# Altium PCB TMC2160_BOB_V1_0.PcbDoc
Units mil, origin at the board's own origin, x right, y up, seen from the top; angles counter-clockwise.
Board outline 1500 x 1100 mil, 4 copper layers (Top, GND, VM, Bottom), stack 63.504 mil thick; 46 components, 52 nets, 171 pads, 147 vias.
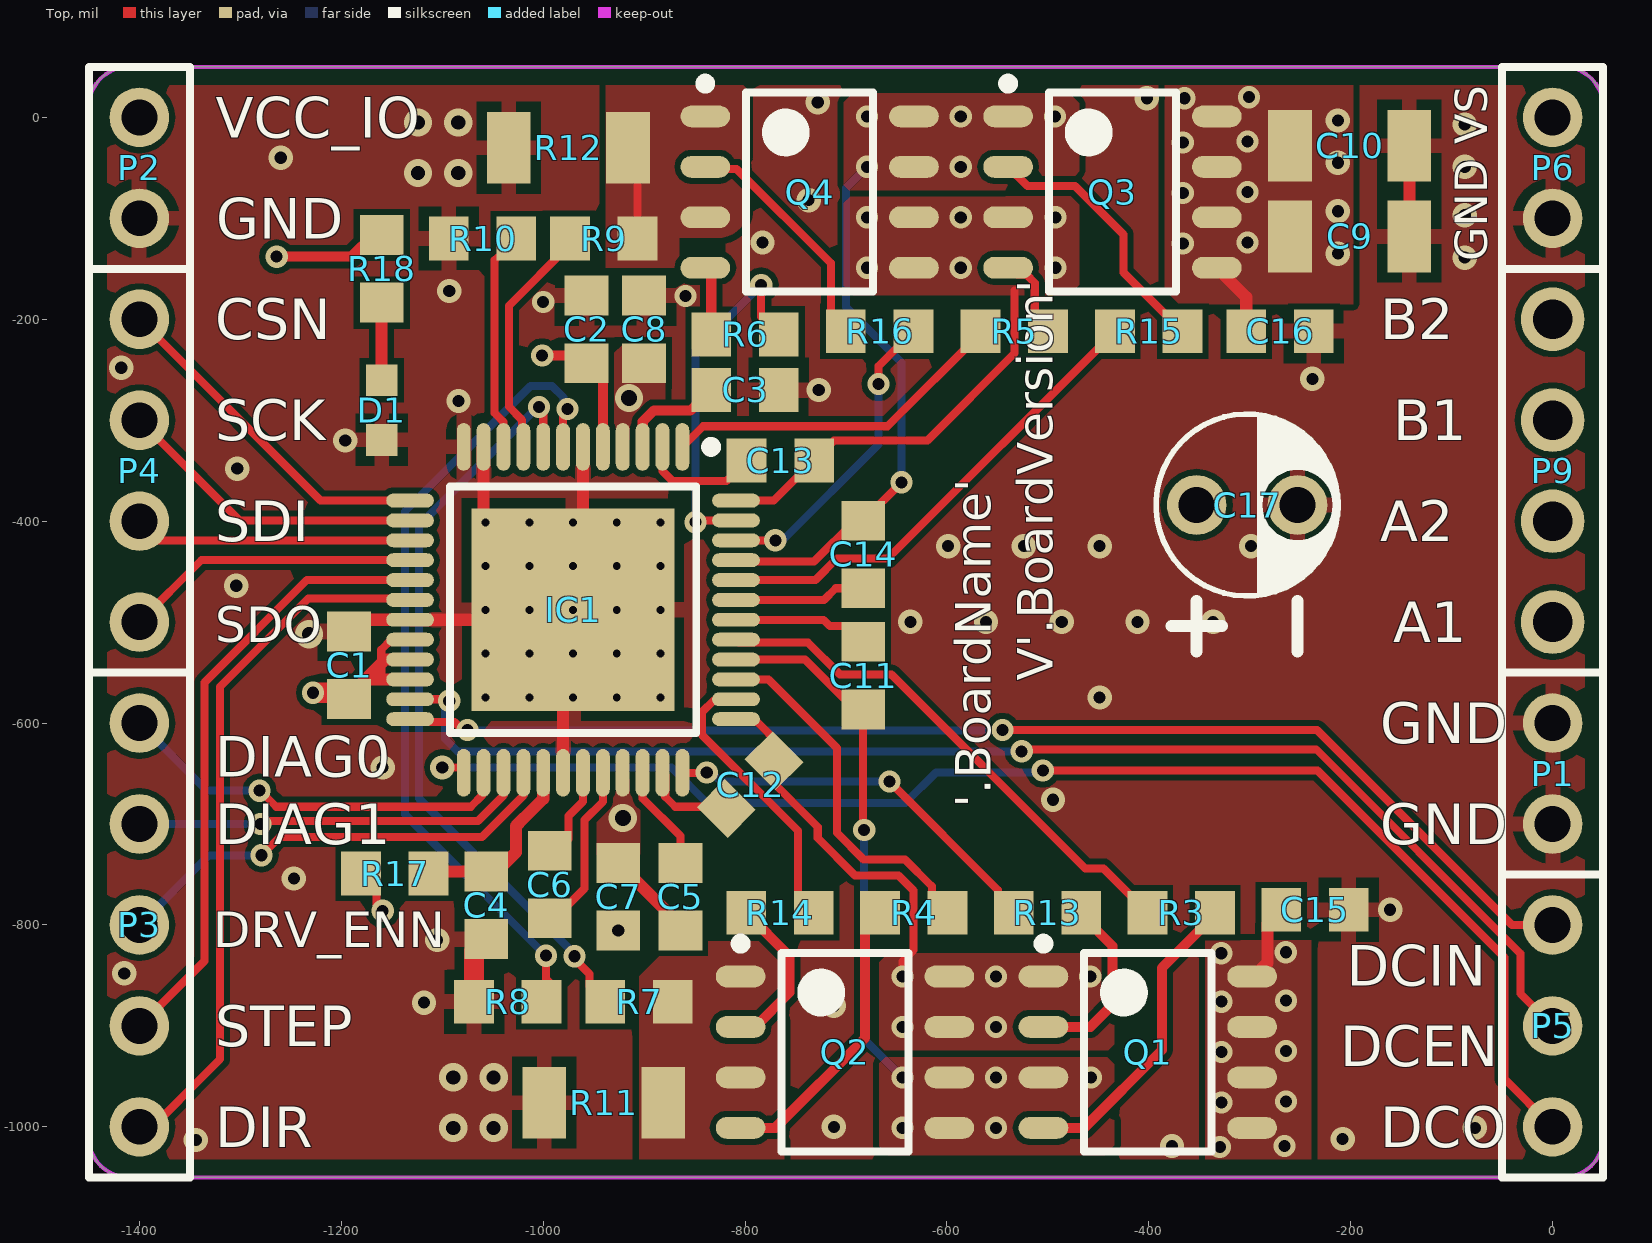
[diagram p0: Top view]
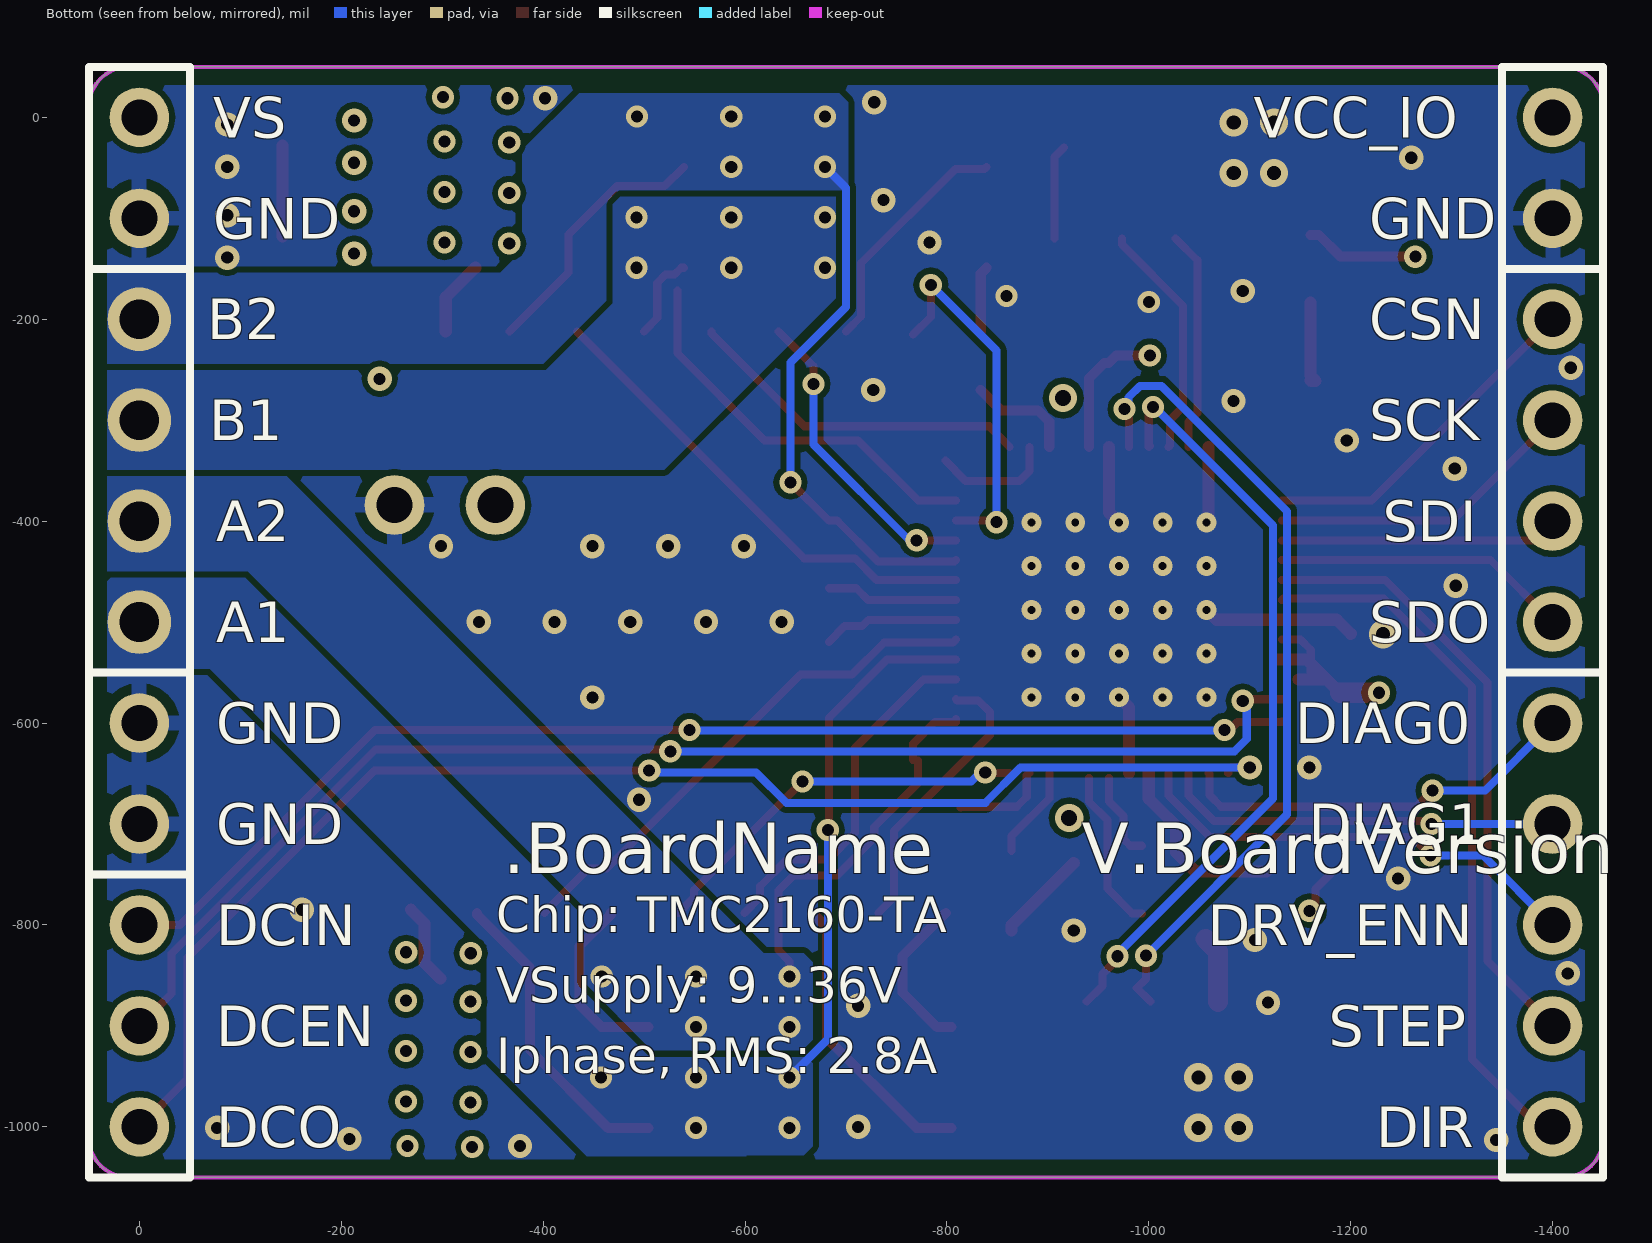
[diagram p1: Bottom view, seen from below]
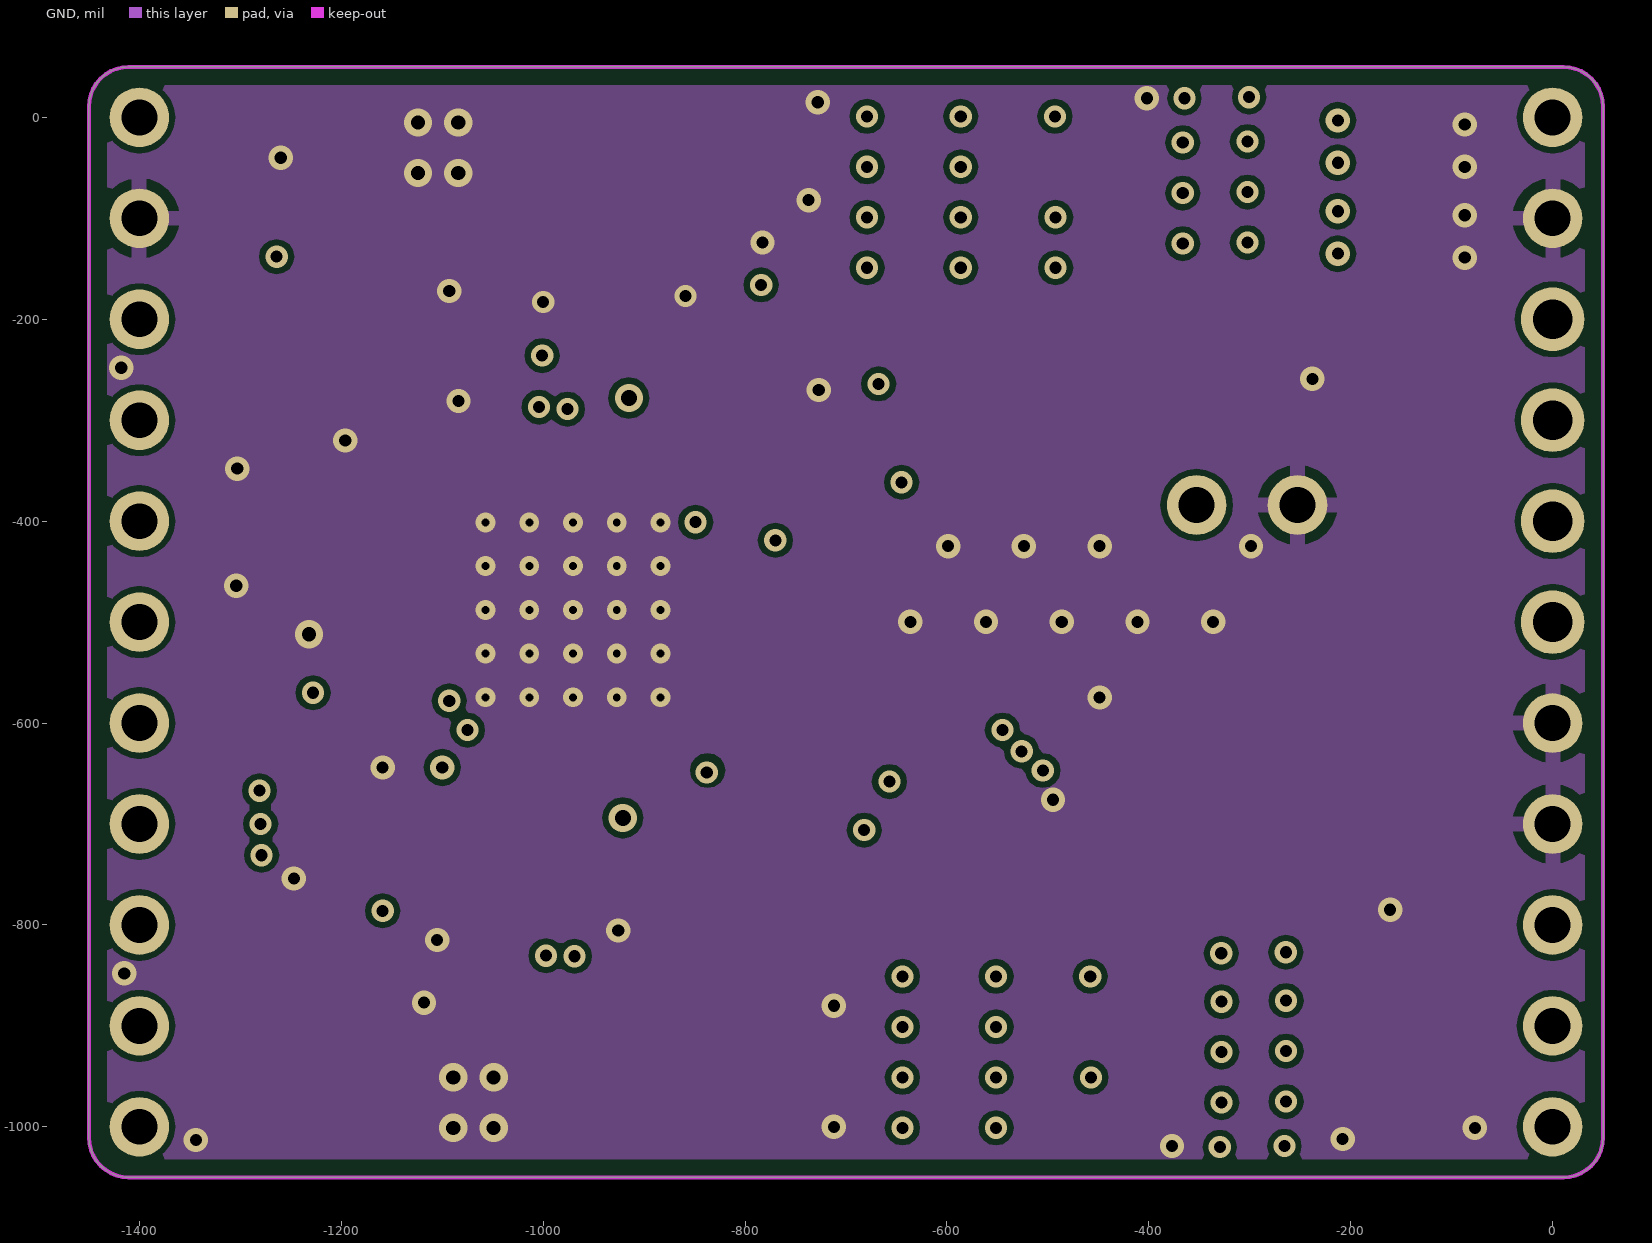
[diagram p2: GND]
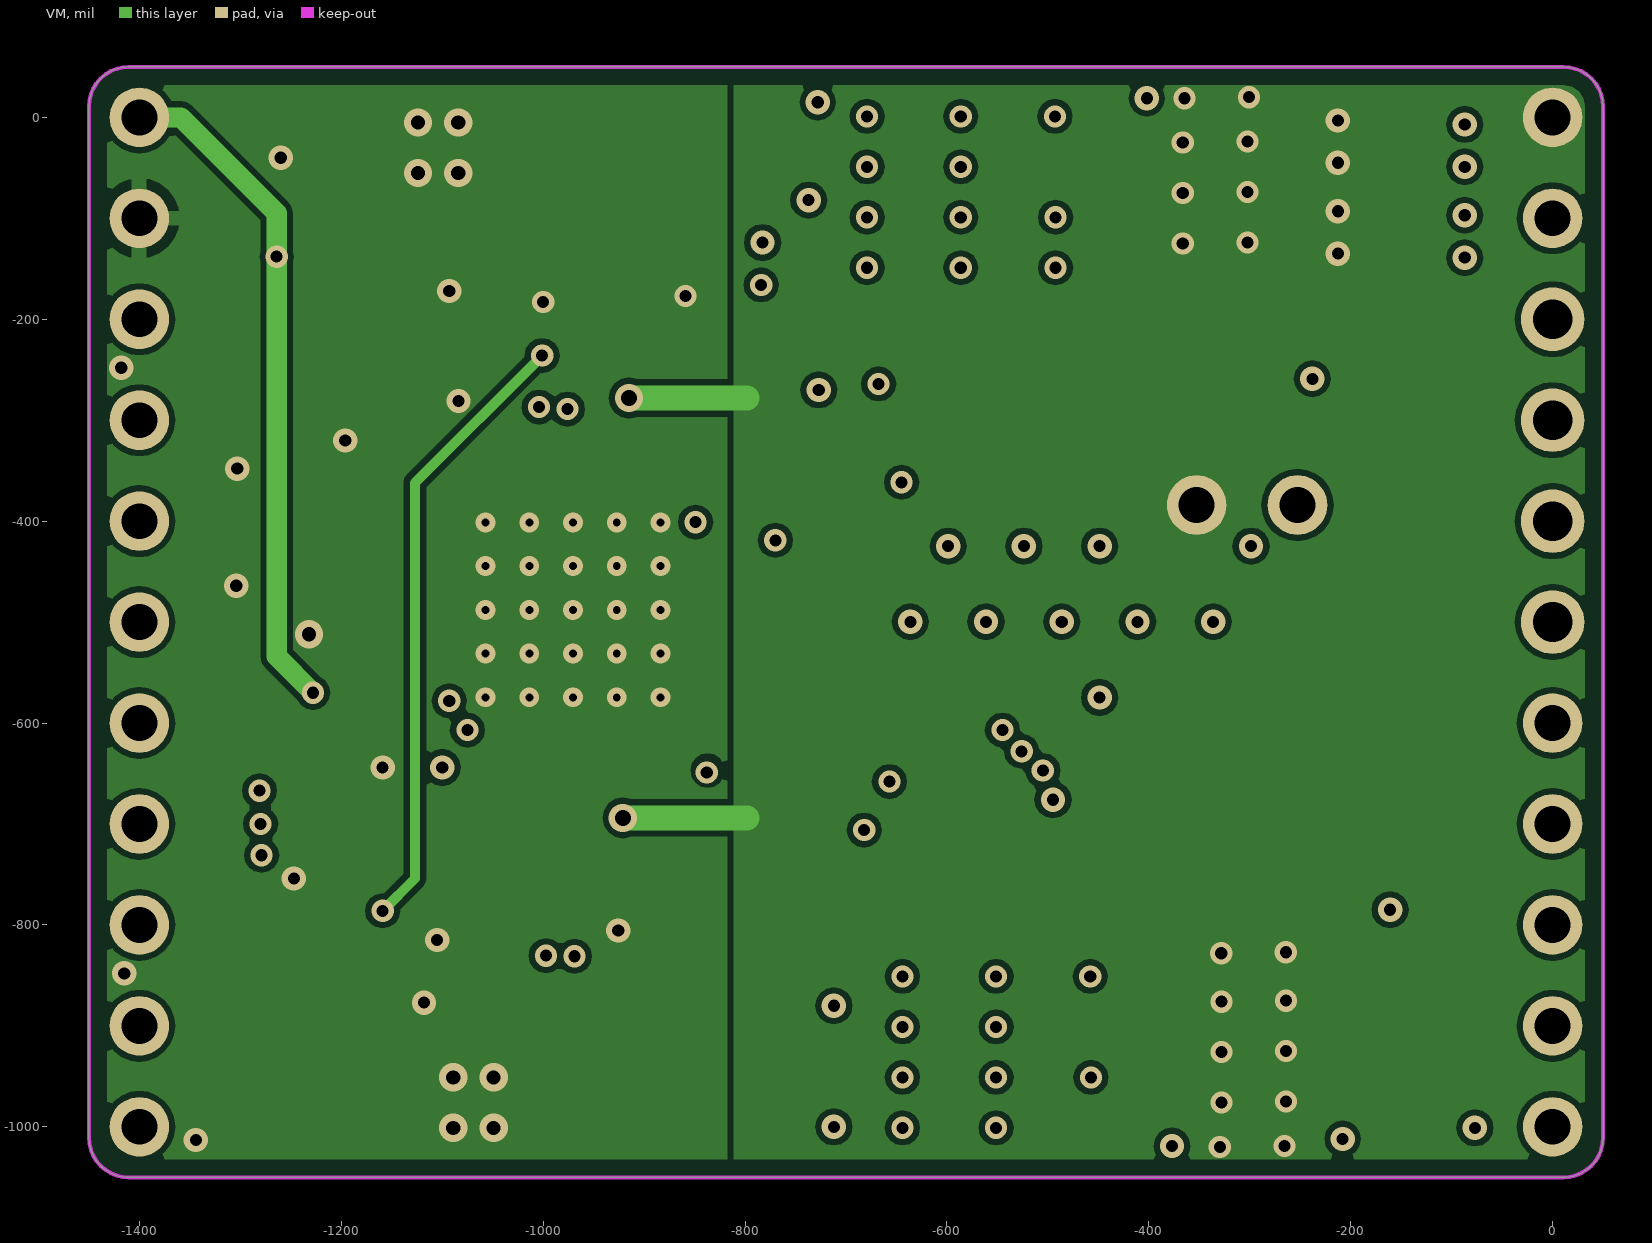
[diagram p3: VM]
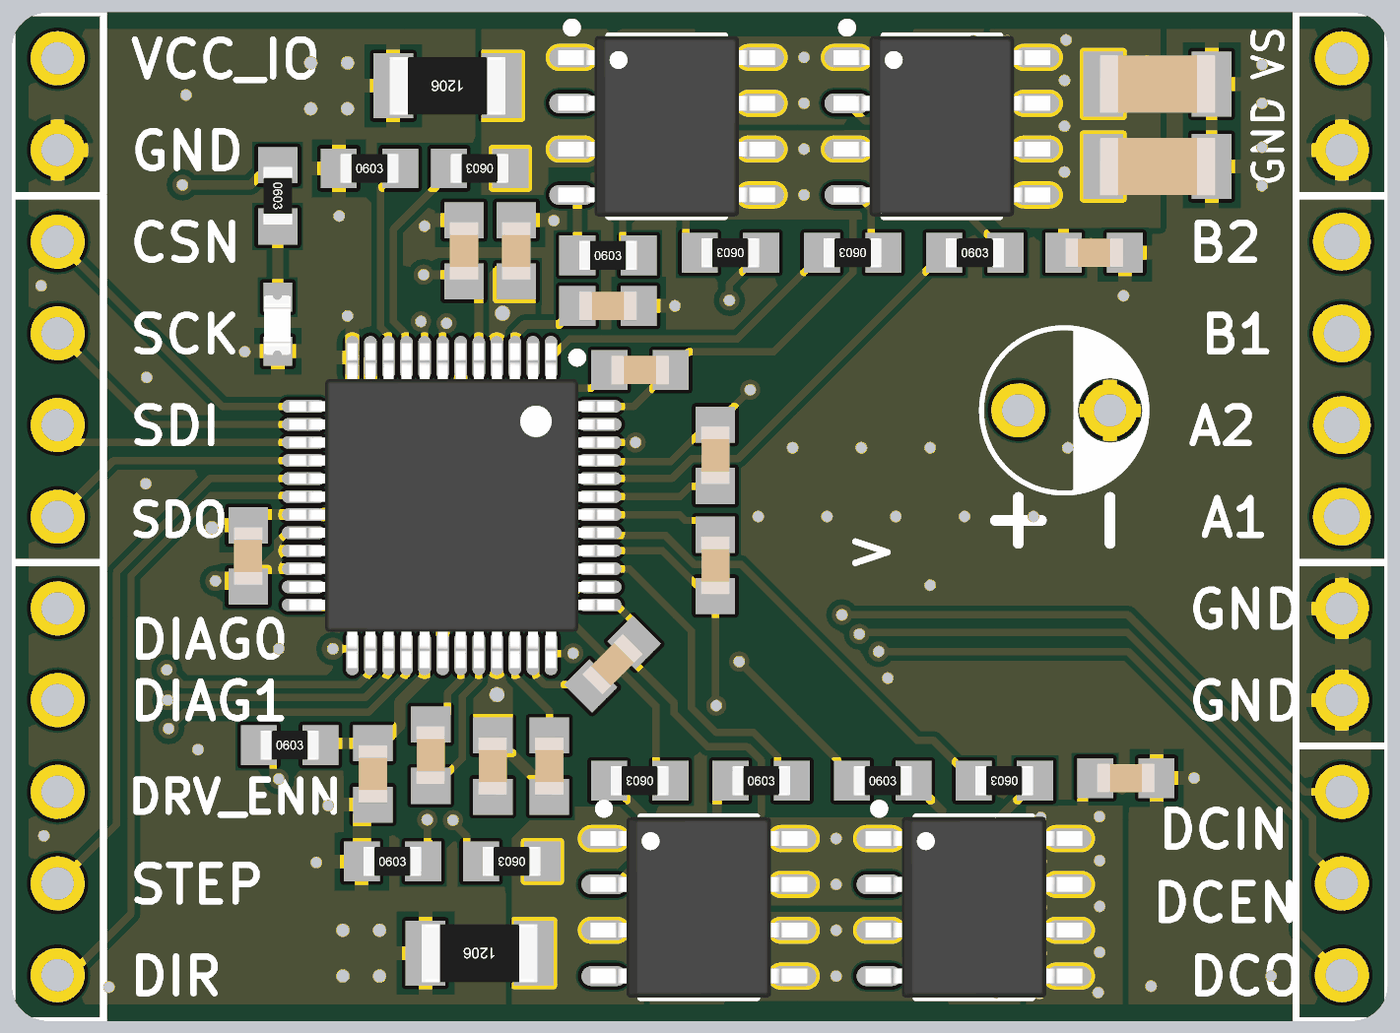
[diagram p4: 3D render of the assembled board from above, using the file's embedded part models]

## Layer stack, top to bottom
Top Solder: solder mask 0.4, Solder Resist, Dk 3.5
Top: signal copper 0.689
Dielectric 1: core 10, FR-4, Dk 4.8
GND: signal copper 1.378
Dielectric 2: prepreg 39.3701, FR-4, Dk 4.2
VM: signal copper 1.378
Dielectric4: core 10, FR-4, Dk 4.2
Bottom: signal copper 0.689
Bottom Solder: solder mask 0.4, Solder Resist, Dk 3.5

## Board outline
-1450,-1010.63 ccw(c-1410.63,-1010.63) -1410.63,-1050 10.63,-1050 ccw(c10.63,-1010.63) 50,-1010.63 50,10.63 ccw(c10.63,10.63) 10.63,50 -1410.63,50 ccw(c-1410.63,10.63) -1450,10.63

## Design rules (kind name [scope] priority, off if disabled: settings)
Clearance BoardOutlineClearance [OnLayer('Keep-Out Layer')] p1: gap=15.75 ignorepadtopadclearanceinfootprint=FALSE except(0: Arc-Hole Track-Hole SMDPad-Hole THPad-Hole Via-Hole Fill-Hole Poly-Hole Region-Hole Text-Hole)
Clearance "Fiducial Clearance" [HasFootprint('FIDUCIAL_40MIL')] p2: gap=26 ignorepadtopadclearanceinfootprint=FALSE except(0: Arc-Hole Track-Hole SMDPad-Hole THPad-Hole Via-Hole Fill-Hole Poly-Hole Region-Hole Text-Hole)
Clearance "Mounting Hole Clearance" [(HoleDiameter >= 110) And  IsPad  And ((PadYSize_AllLayers - HoleDiameter)  <=  1)] p3: gap=30 ignorepadtopadclearanceinfootprint=FALSE except(0: Arc-Hole Track-Hole SMDPad-Hole THPad-Hole Via-Hole Fill-Hole Poly-Hole Region-Hole Text-Hole)
Clearance [All] p4: gap=6 ignorepadtopadclearanceinfootprint=TRUE except(0: Arc-Hole Track-Hole SMDPad-Hole THPad-Hole Via-Hole Fill-Hole Poly-Hole Region-Hole Text-Hole)
ComponentClearance Pinheader2PinheaderClearance [InComponentClass('Pinheader') vs InComponentClass('Pinheader')] p1: gap=0 collisioncheckmode=3 verticalgap=0 showdistances=FALSE
ComponentClearance [All] p2: gap=0 collisioncheckmode=3 verticalgap=100000 showdistances=FALSE
DiffPairsRouting [All] p1 off: maxlimit=10 minlimit=7.5 mostfreqgap=10 toplayer_prefgap=7.5 toplayer_minwidth=7.5 toplayer_maxwidth=7.5 toplayer_prefwidth=7.5 midlayer1_prefgap=7.5 midlayer1_minwidth=7.5 midlayer1_maxwidth=7.5 midlayer1_prefwidth=7.5 midlayer2_mingap=10 midlayer2_minwidth=15 midlayer2_maxwidth=15 midlayer2_prefwidth=15 bottomlayer_prefgap=7.5 bottomlayer_minwidth=7.5 bottomlayer_maxwidth=7.5 bottomlayer_prefwidth=7.5 maxuncoupledlength=500
HoleSize [All] p1: absolutevalues=TRUE maxlimit=100000 minlimit=7.87 maxpercent=80.000 minpercent=20.000
HoleToHoleClearance [All] p1: gap=8 allowstackedmicrovias=TRUE
MatchedLengths "SD_CARD MatchedLengths" [InNetClass('SD_CARD')] p1: tolerance=10 checknetsindiffpair=FALSE checkdiffpairvsdiffpair=TRUE checkxsignals=TRUE checkothers=TRUE
MinimumAnnularRing MinimumViaAnnualRing [All] p1: minimumring=4.92
MinimumSolderMaskSliver STM32_MinimumSolderMaskSliver [(InComponent('STM1') AND InComponent('STM2')) vs (InComponent('STM1') AND InComponent('STM2'))] p1: minsoldermaskwidth=1
MinimumSolderMaskSliver USB_HUB_MinimumSolderMaskSliver [InComponent('USB_HUB')] p2: minsoldermaskwidth=1
MinimumSolderMaskSliver [All] p3 off: minsoldermaskwidth=1.5
PasteMaskExpansion TestPadPasteMaskExpansion [HasFootprint('SMD_TP_2X2_ROUND')] p1: expansion=-78.74
PasteMaskExpansion [All] p2: expansion=0
PolygonConnect SA_SB_PolygonConnect [InNet('SA') OR InNet('SB')] p1: connectstyle=Direct reliefconductorwidth=70 reliefentries=4 polygonreliefangle="90 Angle" airgapwidth=10
PolygonConnect VM_PolygonConnect [InNet('+VM')] p2: connectstyle=Direct reliefconductorwidth=70 reliefentries=4 polygonreliefangle="90 Angle" airgapwidth=10
PolygonConnect ThermalVias [IsVia] p3: connectstyle=Direct reliefconductorwidth=10 reliefentries=4 polygonreliefangle="90 Angle" airgapwidth=10
PolygonConnect MotorOutputConStyle [InNetClass('MotorPowerOut')] p4: connectstyle=Direct reliefconductorwidth=10 reliefentries=4 polygonreliefangle="90 Angle" airgapwidth=10
PolygonConnect [All] p5: connectstyle=Relief reliefconductorwidth=15 reliefentries=4 polygonreliefangle="90 Angle" airgapwidth=10
RoutingVias [All] p1: holewidth=12 width=22 viastyle="Through Hole" minholewidth=12 minwidth=22 maxholewidth=12 maxwidth=50
ShortCircuit [All] p1 off: allowed=FALSE
SilkToBoardRegionClearance [All] p1 off:
SilkToSilkClearance [All] p1 off: silktosilkclearance=10
SilkToSolderMaskClearance [IsPad] p1 off: minsilkscreentomaskgap=10 clearancetoexposedcopper=TRUE
SolderMaskExpansion FiducialSolderMaskExpansion [HasFootprint('FIDUCIAL_40MIL')] p1: expansion=26
SolderMaskExpansion [All] p2: expansion=4
UnRoutedNet [All] p1 off:
Width VIN_Width [InNetClass('PWR_VIN')] p1: maxlimit=300 minlimit=200 preferedwidth=210
Width Other_Width [All] p2: maxlimit=100000 minlimit=8 preferedwidth=11.81 minimp=50.000000 maximp=50.000000 favimp=50.000000
19 further rules are at their usual default settings.

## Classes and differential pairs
net class MotorPowerOut: BMA1 BMA2 BMB1 BMB2

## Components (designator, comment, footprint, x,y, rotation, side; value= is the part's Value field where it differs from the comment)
C1 "100nF" C0603 -1192.26,-542.78 r90 top
C2 "2u2" C0603 -957,-210 r90 top
C3 "2u2" C0603 -800,-270 r180 top
C4 "470nF" C0603 -1056.33,-780.54 r270 top
C5 "100nF" C0603 -864,-772 r90 top
C6 "22nF" C0603 -993.33,-760 r270 top
C7 "100nF" C0603 -925.67,-772 r270 top
C8 "100nF" C0603 -900,-210 r90 top
C9 "10uF/50V/10%" C1206 -201,-118 r180 top
C10 "10uF/50V/10%" C1206 -201,-28 r180 top
C11 "220nF" C0603 -683,-553 r270 top
C12 "220nF" C0603 -795.06,-661 r45 top
C13 "220nF" C0603 -765,-340 r0 top
C14 "220nF" C0603 -683,-433 r90 top
C15 "470nF/50V" C0603 -235.46,-785 r0 top
C16 "470nF/50V" C0603 -270,-212 r0 top
C17 "Cap Pol1" EXT_POL_CAP -352.68,-384 r270 top value="ELKO 100uF/low-ESR"
D1 "LED, Blue, SMD, 20mA, 2.8V, 465 nm" LED_0603 -1160,-290 r270 top
IC1 "TMC2160-TA" TMC5160_TSQFP50P900X900X120_HS-49L -970.42,-487.87 r270 top
P1 "GND" 2_PIN_THT 0,-700 r0 top
P2 "VCC_IO" 2_PIN_THT -1400,-100 r0 top
P3 "MISC" 5_PIN_THT -1400,-1000 r0 top
P4 "SPI" 4_PIN_THT -1400,-200 r180 top
P5 "DCSTEP" 3_PIN_THT 0,-1000 r0 top
P6 "VM" 2_PIN_THT 0,-100 r0 top
P9 "MAB" 4_PIN_THT_1mm_hole 0,-200 r180 top
Q1 "AO4882" SOP127P600X170-8L -401.03,-926 r0 top
Q2 "AO4882" SOP127P600X170-8L -701.03,-926 r0 top
Q3 "AO4882" SOP127P600X170-8L -436.03,-74 r0 top
Q4 "AO4882" SOP127P600X170-8L -736.03,-74 r0 top
R3 "22R / 100mW / 1%" R0603 -367.97,-788 r180 top
R4 "22R / 100mW / 1%" R0603 -632.96,-788 r0 top
R5 "22R / 100mW / 1%" R0603 -533.33,-212 r180 top
R6 "22R / 100mW / 1%" R0603 -800,-215 r0 top
R7 "47R /  / 1%" R0603 -905,-876 r180 top
R8 "47R /  / 1%" R0603 -1035,-876 r0 top
R9 "47R /  / 1%" R0603 -940,-120 r180 top
R10 "47R /  / 1%" R0603 -1060,-120 r0 top
R11 "75mR" R1206 -940,-976 r180 top
R12 "75mR" R1206 -975,-30 r180 top
R13 "22R / 100mW / 1%" R0603 -500.47,-788 r0 top
R14 "22R / 100mW / 1%" R0603 -765.46,-788 r180 top
R15 "22R / 100mW / 1%" R0603 -400,-212 r0 top
R16 "22R / 100mW / 1%" R0603 -666.67,-212 r180 top
R17 "2R2/1%/" R0603 -1147,-749.04 r0 top
R18 "1k" R0603 -1160,-150 r270 top

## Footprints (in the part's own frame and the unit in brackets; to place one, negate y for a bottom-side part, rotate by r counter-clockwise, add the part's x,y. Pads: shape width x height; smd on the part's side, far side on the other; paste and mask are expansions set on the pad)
2_PIN_THT [mm]
  round 1.5 hole 0.9: 1(0,0) 2(0,2.54)
  silkscreen extent -1.27,-1.27 1.27,3.81
3_PIN_THT [mm]
  round 1.5 hole 0.9: 1(0,0) 2(0,2.54) 3(0,5.08)
  silkscreen extent -1.27,-1.27 1.27,6.35
4_PIN_THT [mm]
  round 1.5 hole 0.9: 1(0,0) 2(0,2.54) 3(0,5.08) 4(0,7.62)
  silkscreen extent -1.27,-1.27 1.27,8.89
4_PIN_THT_1mm_hole [mm]
  round 1.6 hole 1: 1(0,0) 2(0,2.54) 3(0,5.08) 4(0,7.62)
  silkscreen extent -1.27,-1.27 1.27,8.89
5_PIN_THT [mm]
  round 1.5 hole 0.9: 1(0,0) 2(0,2.54) 3(0,5.08) 4(0,7.62) 5(0,10.16)
  silkscreen extent -1.27,-1.27 1.27,11.43
C0603 [mm] "0603 ceramic capacitor"
  rect 1x1.1 smd: 1(-0.85,0) 2(0.85,0)
  body extent -0.8,-0.4 0.8,0.4, height 0.8
C1206 [mm] "1206 ceramic capacitor"
  rect 1.1x1.8 smd: 1(-1.5,0) 2(1.5,0)
  body extent -1.6,-0.8 1.6,0.8, height 0.76
EXT_POL_CAP [mm]
  round 1.5 hole 0.9: 1(0,0) 2(0,2.54)
  silkscreen extent -2.29,-1.02 3.68,3.56
LED_0603 [mm]
  rect 0.8x0.8 smd: 1(-0.75,0) 2(0.75,0)
  body extent -0.8,-0.38 0.85,0.35, height 0.68
R0603 [mm] "0603 resistor"
  rect 1x1.1 smd: 1(-0.85,0) 2(0.85,0)
  body extent -0.8,-0.4 0.8,0.4, height 0.45
R1206 [mm] "1206 resistor"
  rect 1.1x1.8 smd: 1(-1.5,0) 2(1.5,0)
  body extent -1.6,-0.8 1.6,0.8, height 0.6
SOP127P600X170-8L [mm] "SOP, 8-Leads, Body 4,90x3,90mm, Pitch 1,27mm, IPC High Density"
  oval 1.25x0.55 smd: 1(-2.625,1.905) 2(-2.625,0.635) 3(-2.625,-0.635) 4(-2.625,-1.905) 5(2.625,-1.905) 6(2.625,-0.635) 7(2.625,0.635) 8(2.625,1.905)
  silkscreen extent -2.75,-2.5 1.6,2.85, body extent -3,-2.5 3,2.5, height 1.7
TMC5160_TSQFP50P900X900X120_HS-49L [mm] "TSQFP, 48-Leads, Body 7,00x7,00mm, Pitch 0,50mm, Thermal Pad 5,10x5,10mm, IPC High Density"
  oval 1.2x0.35 smd mask+0.102: 1(-4.1,2.75) 2(-4.1,2.25) 3(-4.1,1.75) 4(-4.1,1.25) 5(-4.1,0.75) 6(-4.1,0.25) 7(-4.1,-0.25) 8(-4.1,-0.75) 9(-4.1,-1.25) 10(-4.1,-1.75) 11(-4.1,-2.25) 12(-4.1,-2.75) 25(4.1,-2.75) 26(4.1,-2.25) 27(4.1,-1.75) 28(4.1,-1.25) 29(4.1,-0.75) 30(4.1,-0.25) 31(4.1,0.25) 32(4.1,0.75) 33(4.1,1.25) 34(4.1,1.75) 35(4.1,2.25) 36(4.1,2.75)
  oval 0.35x1.2 smd mask+0.102: 13(-2.75,-4.1) 14(-2.25,-4.1) 15(-1.75,-4.1) 16(-1.25,-4.1) 17(-0.75,-4.1) 18(-0.25,-4.1) 19(0.25,-4.1) 20(0.75,-4.1) 21(1.25,-4.1) 22(1.75,-4.1) 23(2.25,-4.1) 24(2.75,-4.1) 37(2.75,4.1) 38(2.25,4.1) 39(1.75,4.1) 40(1.25,4.1) 41(0.75,4.1) 42(0.25,4.1) 43(-0.25,4.1) 44(-0.75,4.1) 45(-1.25,4.1) 46(-1.75,4.1) 47(-2.25,4.1) 48(-2.75,4.1)
  rect 5.1x5.1 smd: 49(0,0)
  silkscreen extent -4.22,-3.1 3.1,3.6, body extent -4.5,-4.5 4.5,4.5, height 1.2

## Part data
C1 C7 C8: library part Capacitor, "Ceramic capacitor", Manufacturer=Multicomp, MPN=MC0603F104M500CT, Voltage rating=50V
C2 C3: library part "2.2 µF, 25 V, ± 10%, X5R, GRM Series", "SMD Multilayer Ceramic Capacitor, 0603 [1608 Metric], 2.2 µF, 25 V, ± 10%, X5R, GRM Series", MPN=GRM188R61E225KA12D, Voltage rating=50V
C4: library part Capacitor, "Ceramic capacitor", MPN=MC0603X474K160CT, Voltage rating=16V
C5: library part Capacitor, "Ceramic capacitor", MPN=MC0603F104M500CT, Voltage rating=50V
C6: library part Capacitor, "Ceramic capacitor", MPN=MC0603B223K500CT, Voltage rating=50V
C9 C10: library part "10 µF, 50 V, ± 20%, X5R, GRM Series", "SMD Multilayer Ceramic Capacitor, 1206 [3216 Metric], 10 µF, 50 V, ± 20%, X5R, GRM Series", Capacitance=10uF, MPN=GRM31CR61H106MA12L, VoltageRating=50V
C11 C12 C13 C14: library part "0.22 µF, 50 V, ± 10%, X7R", "SMD Multilayer Ceramic Capacitor, 0603 [1608 Metric], 0.22 µF, 50 V, ± 10%, X7R, GCM Series", MPN=GCM188R71H224KA64D, Voltage rating=50V
C15 C16: library part "0.47 µF, 50 V, ± 10%, X7R, C Series", "SMD Multilayer Ceramic Capacitor, 0603 [1608 Metric], 0.47 µF, 50 V, ± 10%, X7R, C Series", Capacitance=470nF, MPN=C1608X7R1H474K080AC, VoltageRating=50V
C17: "Polarized Capacitor (Radial)"
D1: Colour=Blue, Current rating=20mA, MPN=LTST-C191TBKT-5A
IC1: Manufacturer=TRINAMIC
P1 P2 P6: library part "Header 2", "Header, 2-Pin"
P3: library part "Header 5", "Header, 5-Pin"
P4: library part "Header 4", "Header, 4-Pin"
P5: library part "Header 3", "Header, 3-Pin"
P9: library part "Wire-To-Board Connector, 2.5 mm, 4 Contacts, Header, EH Series, Through Hole, 1 Rows", "Wire-To-Board Connector, 2.5 mm, 4 Contacts, Header, EH Series, Through Hole, 1 Rows", MPN=B4B-EH-A
Q1 Q2 Q3 Q4: library part "AO4882 MOSFET 2N-CH 40V 8A 8SOIC", "Mosfet Array 2 N-Channel (Dual) 40V 8A 2W Surface Mount 8-SOIC"
R3 R4 R5 R6 R13 R14 R15 R16: library part "22 ohm, 50 V, 0603 [1608 Metric], 100 mW, ± 1%, MCWR Series", "SMD Chip Resistor, Thick Film, 22 ohm, 50 V, 0603 [1608 Metric], 100 mW, ± 1%, MCWR Series", MPN=MCWR06X22R0FTLV, PowerRating=100mW, Resistance=22R, Temp coefficient=*ppm
R7 R8 R9 R10: library part "47 ohm, 75 V, 0603 [1608 Metric], 100 mW, ± 1%, MCSR 06 Series", "SMD Chip Resistor, Ceramic, 47 ohm, 75 V, 0603 [1608 Metric], 100 mW, ± 1%, MCSR 06 Series", MPN=MCSR06X47R0FTL, Resistance=47R, Temp coefficient=*ppm
R11 R12: library part "R_SENS, 0.075 ohm, 1206, 1W, ± 1%, ERJ Series", "SMD Chip Resistor, Thick Film, Current Sense Resistors - SMD 1W 0.075ohm 1%", MPN=ERJ-8BWFR075V, PowerRating=1W, Temp coefficient=*ppm, VoltageRating=50V
R17: library part Resistor, "Resistor", MPN=MC0063W060312R2, Power rating=*mW, Resistance=2R2, Temp coefficient=*ppm, Voltage rating=*V
R18: library part "1 kohm, 50 V, 0603 [1608 Metric], 63 mW, ± 1%, MC Series", "1 kohm, 50 V, 0603 [1608 Metric], 63 mW, ± 1%, MC Series", MPN=MC0063W060311K, PowerRating=63mW, Temp coefficient=*ppm, VoltageRating=50V

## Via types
v1: diameter 22, hole 12, Top to Bottom, tented both sides, 65 vias
v2: diameter 24.1, hole 12, Top to Bottom, tented both sides, 29 vias
v3: diameter 19.68, hole 7.87, Top to Bottom, tented bottom, 25 vias
v4: diameter 24, hole 12, Top to Bottom, tented both sides, 17 vias
v5: diameter 28, hole 14, Top to Bottom, tented both sides, 9 vias
v6: diameter 28, hole 16, Top to Bottom, tented both sides, 2 vias

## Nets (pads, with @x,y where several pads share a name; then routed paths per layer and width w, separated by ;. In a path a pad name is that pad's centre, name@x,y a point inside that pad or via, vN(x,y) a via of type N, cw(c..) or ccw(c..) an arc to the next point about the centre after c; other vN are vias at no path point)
5V_OUT: C2.1 IC1.5 R17.1 | length 798.9
  Top w8: R17.1 -1165,-764.5 -1165,-780 v1(-1159,-786)
  Top w10: v1(-1001,-236) -967.46,-236 -960,-243.46 -955.57,-243.46 -940.89,-258.15 IC1.5
  VM w10: v1(-1159,-786) -1127,-754 -1127,-362 v1(-1001,-236)
12VOUT: C3.2 IC1.3 | length 106.3
  Top w10: IC1.3 -901.32,-326.45 -901.32,-301.32 -890.23,-290.23 -854.08,-290.23 -853.88,-290.42 C3.2
+VM: C5.1 C7.1 C8.1 C9.2 C10.2 C15.1 C16.1 C17.1 IC1.4 IC1.33 P6.2 Q1.5 Q1.6 Q1.7 Q1.8 Q3.5 Q3.6 Q3.7 Q3.8 | length 487.7
  Top w12: C7.1 -864,-800.2 C5.1 ; Q3.5 -303.46,-178.22 C16.1 ; Q1.8@-298,-853 -282.61,-837.61 -282.61,-798.69 C15.1
  VM w25: v6(-921.06,-694) -798,-694 ; v6(-915.06,-278) -798,-278
  other v1: -329.68,-1020 -265.68,-1019 -328,-976 -264,-975 -328,-926 -264,-925 -328,-876 -264,-875 -328.32,-828 -264.32,-827 -366.37,-125 -302.37,-124 -366.37,-75 -302.37,-74 -366.37,-25 -302.37,-24 -364.68,19 -300.68,20
  other v4: -212.79,-135 -212.79,-93 -212.79,-45 -212.79,-3
BMA1: C11.2 IC1.40 P9.4 Q1.3 Q2.5 Q2.6 | length 522.8
  Top w8: IC1.40 -740.74,-537.08 -683,-594.81 -683,-705 v1(-682,-706)
  Bottom w8: v1(-682,-706) -682,-911.69 -682.68,-912.37 v1(-644.06,-951)
  other v1: -644.06,-1001 -551.31,-1001 -551.31,-951 -457.44,-951
BMA2: C12.2 IC1.37 P9.3 Q1.1 Q2.7 Q2.8 | length 371
  Top w8: IC1.37 -809,-599.02 -787.98,-599.02 -766.34,-620.66 C12.2@-766.34,-636.34 ; C12.2 -771.39,-659.61 -728,-703 -728,-714 -691,-751 -647.95,-751 -633,-765.95 -633,-825 -644.06,-836.06 v1(-644.06,-851)
  other v1: -644.06,-901 -551.31,-901 -551.31,-851 -458.01,-851
BMB1: C13.2 IC1.48 P9.2 Q3.3 Q4.5 Q4.6 | length 398.7
  Top w8: IC1.48 -771.6,-379.6 -712,-320 -619.32,-320 -533,-233.68 -533,-171.38
  other v1: -679.06,-149 -586.31,-149 -492.44,-149 -679.06,-99 -586.31,-99 -492.44,-99
BMB2: C14.2 IC1.45 P9.1 Q3.1 Q4.7 Q4.8 | length 541.1
  Top w8: IC1.45 -807.68,-439.97 -731.78,-439.97 -691.35,-399.54 C14.2 v1(-645,-361.54)
  Bottom w8: v1(-679.06,-49) -700.06,-70 -700.06,-187.74 -645,-242.8 v1(-645,-361.54)
  other v1: -586.31,-49 -679.06,1 -586.31,1 -493.01,1
CA1: C11.1 IC1.42 | length 135
  Top w8: IC1.42 -722.35,-497.71 -716.06,-504 -698.54,-504 C11.1
CA2: C12.1 IC1.35 | length 94.7
  Top w8: IC1.35 -879.04,-652.08 -879.04,-673.01 -869.14,-682.9 -814.42,-682.9 C12.1@-813.66,-683.66
CB1: C13.1 IC1.2 | length 119.5
  Top w8: IC1.2 -881.83,-350.21 -871.97,-360.07 -818.53,-360.07 C13.1
CB2: C14.1 IC1.43 | length 130.8
  Top w8: IC1.43 -721.71,-478.02 -710.15,-466.46 C14.1
CSN: IC1.13 P4.1 | length 342.6
  Top w8: P4.1 -1220.4,-379.6 IC1.13
DCEN: IC1.23 P5.2 | length 1326.6
  Top w8: IC1.23 -1094.55,-576.45 v1(-1093,-578) ; v1(-526,-628) -528,-628 -530,-626 -234.2,-626 -32,-828.2 -32,-868 P5.2
  Bottom w8: v1(-1093,-578) -1093,-581.79 -1097,-585.79 -1097,-615.82 -1084.82,-628 v1(-526,-628)
DCIN: IC1.24 P5.3 | length 1221.4
  Top w8: IC1.24@-1131.83,-598.26 -1131.09,-599 -1087.66,-599 -1076,-610.66 -1075,-609.66 v1(-1075,-607) ; v1(-545,-607) -233.4,-607 -40.4,-800 P5.3
  Bottom w8: v1(-1075,-607) -1075.5,-607.5 -545.5,-607.5 v1(-545,-607)
DCO: IC1.25 P5.1 | length 1369.3
  Top w8: v2(-1100,-644) -1081.35,-644 -1078.68,-646.67 IC1.25 ; v1(-505,-647) -233,-647 -47.68,-832.31 -47.68,-952.32 P5.1
  Bottom w8: v2(-1100,-644) -873,-644 -838,-679 -641,-679 -611,-649 -507,-649 v1(-505,-647)
DIAG0: IC1.26 P3.5 | length 401.5
  Top w8: v1(-1281,-667) -1280.28,-667 -1264.38,-682.9 -1071.69,-682.9 -1060.1,-671.32 -1060.1,-650.39 IC1.26
  Bottom w8: P3.5 -1333,-667 v1(-1281,-667)
DIAG1: IC1.27 P3.4 | length 394.9
  Top w8: v1(-1280,-700) -1277,-697 -1064.53,-697 -1039.31,-671.78 IC1.27
  Bottom w8: P3.4 v1(-1280,-700)
DIR: IC1.18 P3.1 | length 707
  Top w8: P3.1@-1400,-1013 -1320,-933 -1320,-564 -1232.71,-476.71 -1133.15,-476.71 IC1.18
DRV_ENN: IC1.28 P3.3 | length 456
  Top w8: v1(-1279,-731) -1261,-713 -1060.73,-713 -1019.63,-671.89 IC1.28
  Bottom w8: P3.3 -1331,-731 v1(-1279,-731)
GND: C1.2 C2.2 C3.1 C4.2 C7.2 C8.2 C9.1 C10.1 C15.2 C16.2 C17.2 D1.2 IC1.6 IC1.11 IC1.12 IC1.19 IC1.30 IC1.49 P1.1 P1.2 P2.1 P6.1 R8.1 R10.1 R11.2 R12.2 | length 543.2
  Top w12: C1.2@-1200,-511.54 -1186.17,-497.71 IC1.19 -1066.87,-497.71 v3(-1057.03,-487.87) ; IC1.11 -1059,-399.28 v3(-1057.03,-401.25) ; IC1.30 -980.26,-584.32 v3(-970.42,-574.48) ; v3(-970.42,-401.25) -960.57,-391.41 IC1.6 ; C9.1 C10.1
  Top w20: R8.1 -1068.46,-826.13 C4.2
  other v1: -1000,-183 -859.06,-177
  other v2: -377,-1019 -1344,-1013 -208,-1012 -77,-1001 -712,-1000 -712,-880 -1415,-848 -161,-785 -1247,-754 -495,-676 -1159,-644 -448.77,-574.73 -636.27,-499.73 -561.27,-499.73 -486.27,-499.73 -411.27,-499.73 -336.27,-499.73 -1304,-464 -598.77,-424.73 -523.77,-424.73 -448.77,-424.73 -298.77,-424.73 -1303,-348 -1418,-248 -737,-82 -1260,-40 -728,15 -402,19
  other v3: -1057.03,-574.48 -1013.72,-574.48 -927.11,-574.48 -883.8,-574.48 -1057.03,-531.17 -1013.72,-531.17 -970.42,-531.17 -927.11,-531.17 -883.8,-531.17 -1013.72,-487.87 -970.42,-487.87 -927.11,-487.87 -883.8,-487.87 -1057.03,-444.56 -1013.72,-444.56 -970.42,-444.56 -927.11,-444.56 -883.8,-444.56 -1013.72,-401.25 -927.11,-401.25 -883.8,-401.25
  other v4: -1118.06,-877 -1105,-815 -925.67,-805.46 -1196,-320 -1084,-281 -727,-270 -238.06,-259 -1093.06,-172 -87.06,-139 -782.68,-124 -87.06,-97 -87.06,-49 -87.06,-7
  other v5: -1089.06,-1001 -1049.06,-1001 -1089.06,-951 -1049.06,-951 -1232,-512 -1124.06,-55 -1084.06,-55 -1124.06,-5 -1084.06,-5
HA1: IC1.41 R3.2 | length 519.9
  Top w8: IC1.41 -806.2,-520.19 -737.83,-520.19 -706.02,-552 -655,-552 -463,-744 -445.06,-744 -401.43,-787.63 R3.2
HA2: IC1.36 R13.1 | length 393.1
  Top w8: IC1.36 -838.28,-649.28 v1(-838,-649) ; v1(-657,-658) -549.61,-765.39 -549.61,-772.31 R13.1
  Bottom w8: v1(-838,-649) -838,-647.94 -837,-646.94 -836.06,-646 -824.06,-658 v1(-657,-658)
HB1: IC1.1 R5.2 | length 343.9
  Top w8: IC1.1 -841.7,-306 -658.83,-306 -566.8,-213.97 R5.2
HB2: IC1.44 R15.1 | length 477.6
  Top w8: IC1.44 -730.35,-458.34 -708.8,-436.78 -658.24,-436.78 R15.1
LA1: IC1.39 R4.2 | length 360.9
  Top w8: IC1.39 -776.87,-556.76 -709,-624.63 -709,-708.7 -682.7,-735 -641.68,-735 -615,-761.68 -615,-772.5 R4.2
LA2: IC1.38 R14.1 | length 283.6
  Top w8: IC1.38 -810.1,-577.55 -831.04,-577.55 -842.62,-589.14 -842.62,-611.74 -747.69,-706.67 -747.69,-772.31 R14.1
LB1: IC1.47 R6.2 | length 355.9
  Top w8: v1(-849.06,-401) -847.34,-399.28 IC1.47 ; v1@-784.06,-169 -784.06,-197.48 R6.2
  Bottom w8: v1(-849.06,-401) -849.06,-231 v1(-784.06,-166)
LB2: IC1.46 R16.1 | length 306.9
  Top w8: IC1.46 v1(-770,-418.97) ; v1(-667.68,-264) -667.68,-246.48 R16.1
  Bottom w8: v1(-770,-418.97) -762.65,-418.97 -667.68,-324 v1(-667.68,-264)
NetC5_2: C5.2 IC1.34 | length 92.8
  Top w8: IC1.34 -901.52,-674.54 -864,-712.05 C5.2@-864,-726.54
NetC6_1: C6.1 IC1.31 | length 87.7
  Top w8: C6.1@-993.33,-721.54 -981.54,-721.54 -975,-715 -975,-692.2 -960.57,-677.77 IC1.31@-960.57,-654.28
NetC6_2: C6.2 IC1.32 | length 161.7
  Top w8: C6.2@-993.33,-788.46 -983.46,-788.46 -958.92,-763.92 -958.92,-695.92 -940.89,-677.89 IC1.32@-940.89,-654.28
NetD1_1: D1.1 R18.2 | length 84.8
  Top w12: D1.1 -1160.53,-261 -1165,-261 -1160,-256 R18.2
NetQ1_2: Q1.2 R13.2 | length 181.3
  Top w10: Q1.2 -458.06,-901 -436.01,-878.95 -436.01,-820.96 -467,-789.97 R13.2
NetQ1_4: Q1.4 R3.1 | length 307
  Top w10: Q1.4 -464.06,-1001 -387,-923.94 -387,-842.47 -334.5,-789.97 R3.1
NetQ2_2: Q2.2 R14.2 | length 159.2
  Top w10: Q2.2 -790,-901 -756,-867 -756,-830.93 R14.2
NetQ2_4: Q2.4 R4.1 | length 290.3
  Top w10: Q2.4 -770,-1001 -681.06,-912.06 -681.06,-802.63 R4.1
NetQ3_2: Q3.2 R15.2 | length 262.3
  Top w8: Q3.2 -520.38,-68 -473,-68 -425,-116 -425,-153.54 R15.2
NetQ3_4: Q3.4 R5.1 | length 86
  Top w8: Q3.4 -536.82,-149 -530,-155.83 -521.2,-155.83 -513,-164.03 -513,-198.87 R5.1
NetQ4_2: Q4.2 R16.2 | length 237.6
  Top w8: Q4.2 -837.38,-51 -808.47,-51 -715.06,-144.42 -715.06,-197.08 R16.2
NetQ4_4: Q4.4 R6.1 | length 65.4
  Top w10: Q4.4 -833.46,-154.91 R6.1@-833.46,-212
SA: Q2.1 Q2.3 R7.1 R11.1
SB: Q4.1 Q4.3 R9.1 R12.1 | length 93.9
  Top w8: R12.1 -906.54,-39.41 R9.1
SCK: IC1.14 P4.2 | length 309.3
  Top w8: P4.2 -1300.72,-399.28 IC1.14
SDI: IC1.15 P4.3 | length 276
  Top w8: P4.3 -1381.03,-418.97 IC1.15
SDO: IC1.16 P4.4 | length 293.6
  Top w8: P4.4 -1338.65,-438.65 IC1.16
SRAH: IC1.8 R7.2 | length 760.7
  Top w8: v1(-1004,-287) v1(-1004,-287) -999.94,-287.06 IC1.8 IC1.8@-1001,-325.39 ; v1(-969.06,-831) -969.06,-833.72 -954.15,-848.62 -954.15,-860.31 R7.2
  Bottom w8: v1(-1004,-287) -1005.74,-287 -1122.95,-404.21 -1122.95,-674.86 -969.06,-828.76 v1(-969.06,-831)
SRAL: IC1.7 R8.2 | length 818.7
  Top w8: R8.2 -988.06,-862.52 -997.06,-853.52 v1(-997.06,-830.46) ; IC1.7 -980.26,-293.26 v1(-976,-289)
  Bottom w8: v1(-997.06,-830.46) -1136.95,-690.56 -1136.95,-390.25 -1012.7,-266 -991.3,-266 -980,-277.3 -980,-281.21 -976,-285.21 v1(-976,-289)
SRBH: IC1.9 R9.2 | length 237.5
  Top w8: IC1.9 -1020.94,-325.13 -1020.94,-299.75 -1034,-286.7 -1034,-186.62 -973.46,-126.09 R9.2
SRBL: IC1.10 R10.2 | length 218.9
  Top w8: IC1.10 -1039.31,-301.71 -1048,-293.02 -1048,-141.46 R10.2
STEP: IC1.17 P3.2 | length 612.7
  Top w8: P3.2 -1335.6,-835.6 -1335.6,-559.8 -1234.14,-458.34 IC1.17
VCC: C4.1 IC1.29 R17.2 | length 187.6
  Top w12: R17.2@-1116.67,-747.07 C4.1 -1046.07,-747.07 -1026.99,-727.99 -1026.99,-701.88 -1019.96,-694.85 -1019.85,-694.85 -999.94,-674.94 IC1.29
VCC_IO: C1.1 IC1.20 IC1.21 IC1.22 P2.2 R18.1 | length 981.7
  Top w8: -1160.39,-541 -1160.39,-527.39 -1150.39,-517.39 IC1.20 ; -1160,-556.76 -1160,-540.61 -1156.39,-537 ; IC1.21 IC1.21@-1130.64,-538.27
  Top w10: v1(-1264,-138) -1190,-138 -1168.54,-116.54 R18.1
  Top w12: C1.1@-1189.39,-570 -1160.39,-541 -1160,-540.61 ; C1.1@-1174,-556.76 -1160,-556.76 IC1.22@-1148.46,-556.76 ; -1156.39,-537 IC1.21@-1127.83,-537
  Top w20: v1(-1228,-570) C1.1@-1189.39,-570
  VM w20: P2.2 -1359,0 -1264,-95 v1(-1264,-138) -1264,-534 v1(-1228,-570)

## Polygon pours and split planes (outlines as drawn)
GND on Top "GND_L01_P035" (solid, remove dead copper, pour order 97): -1450,-1010.63 -1450,10.63 cw(c-1410.63,10.63) -1410.63,50 10.63,50 cw(c10.63,10.63) 50,10.63 50,-1010.63 cw(c10.63,-1010.63) 10.63,-1050 -1410.63,-1050 cw(c-1410.63,-1010.63)
BMB1 on Top "BMB1_L01_P035" (solid, pour order 92): -695.24,-78 -702.05,-84.81 -702.06,-167 -693.05,-176 -479.06,-176 -469.06,-166 -469.06,-86 -477.05,-78
+VM on Top "+VM_L01_P038" (solid, pour order 95): -344.12,-1050 -344.12,-815 -239,-815 -239,-1050
BMA1 on Top "BMB1_L01_P035" (solid, pour order 91): -661.24,-931 -667.05,-936.81 -667.06,-1019 -658.05,-1028 -444.06,-1028 -434.06,-1018 -434.06,-938 -441.05,-931
BMB2 on Top "BMB1_L01_P035" (solid, pour order 89): -693.24,24 -702.05,15.19 -702.06,-67 -697.06,-72 -475.05,-72 -469.06,-66 -469.06,14 -479.06,24
SB on Top "SB_L01_P043" (solid, pour order 93): -938.06,32 -938.06,-149 -865.06,-149 -865.06,-119 -825.05,-119 ccw(c-825.05,-92.22) -798.28,-92.22 -798.28,32
SA on Top "SA_L01_P042" (solid, pour order 96): -905.06,-1050 -905.06,-851.05 -870.16,-816.15 -786.64,-816.15 -761.06,-841.74 -761.06,-1050
BMA2 on Top "BMB1_L01_P035" (solid, pour order 90): -658.24,-828 -667.05,-836.81 -667.06,-919 -662.06,-924 -440.05,-924 -434.06,-918 -434.06,-838 -444.06,-828
+VM on Top "+VM_L01_P038" (solid, pour order 94): -384,50 -384,-171 -370,-185 -197.68,-185 -197.68,50
+VM on Top "+VM_L01_P039" (solid, pour order 87): -921.2,-649.28 -947,-675.08 -947,-731 -905,-731 -904,-730 -904,-666.49
+VM on Top "+VM_L01_P037" (solid, pour order 88): -921.2,-326.45 -926.55,-326.45 -935,-318 -935,-239 -921,-225 -884,-225 -879,-230 -879,-279 -890.23,-290.23 -890.23,-295.47
GND on Bottom "GND_L04_P039" (solid, remove dead copper, pour order 108): -1450,-1010.63 -1450,10.63 cw(c-1410.63,10.63) -1410.63,50 10.63,50 cw(c10.63,10.63) 50,10.63 50,-1010.63 cw(c10.63,-1010.63) 10.63,-1050 -1410.63,-1050 cw(c-1410.63,-1010.63)
BMB2 on Bottom "BMB2_L04_P107" (solid, pour order 107): 50,-154 -357.32,-154 -379.05,-132.27 -379.06,-32.63 -435.68,24 -495.68,24 -475.06,3.37 -475.05,-171.63 -402.68,-244 50,-244
BMA1 on Bottom "BMA1_L04_P106" (solid, pour order 106): 50,-546 -69.68,-546 -344,-820.32 -344,-930 -443,-1029 -607.68,-1029 -442.68,-864 -442.68,-794 -104.69,-456 50,-456
BMA2 on Bottom "BMA2_L04_P105" (solid, pour order 105): -440,-844.36 -440,-782.13 -107.37,-449.51 49.49,-449.51 50,-449 50,-354 -144.72,-354 -618.72,-828 -658.24,-828 -585.24,-901 -494.68,-901 -467.68,-874
BMA1 on Bottom "BMB1_L01_P035" (solid, pour order 102): -661.24,-931 -667.05,-936.81 -667.06,-1019 -658.05,-1028 -444.06,-1028 -434.06,-1018 -434.06,-938 -441.05,-931
BMA2 on Bottom "BMB1_L01_P035" (solid, pour order 101): -658.24,-828 -667.05,-836.81 -667.06,-919 -662.06,-924 -507.68,-924 -440,-856.31 -440,-832.06 -444.06,-828
BMB2 on Bottom "BMB1_L01_P035" (solid, pour order 100): -693.24,24 -702.05,15.19 -702.06,-67 -697.06,-72 -475.05,-72 -469.06,-66 -469.06,14 -479.06,24
BMB1 on Bottom "BMB1_L01_P035" (solid, pour order 104): -695.24,-78 -702.05,-84.81 -702.06,-167 -693.05,-176 -479.06,-176 -469.06,-166 -469.06,-86 -477.05,-78
BMB1 on Bottom "BMB1_L04_P103" (solid, pour order 103): -702.06,-166.91 -519.97,-349 50,-349 50,-249 48.51,-250.49 -402.68,-250.49 -469.06,-184.12 -469.06,-147
GND on VM "GND_L03_P109" (solid, pour order 109): -589,-1050 -589,50 -1410.63,50 ccw(c-1410.63,10.63) -1450,10.63 -1450,-1010.63 ccw(c-1410.63,-1010.63) -1410.63,-1050
+VM on VM "+VM_L03_P050" (solid, pour order 99): -811,-1050 -811,50 10.63,50 cw(c10.63,10.63) 50,10.63 50,-1010.63 cw(c10.63,-1010.63) 10.63,-1050
GND on GND "GND_L02_P037" (solid, pour order 98): -1450,-1010.63 -1450,10.63 cw(c-1410.63,10.63) -1410.63,50 10.63,50 cw(c10.63,10.63) 50,10.63 50,-1010.63 cw(c10.63,-1010.63) 10.63,-1050 -1410.63,-1050 cw(c-1410.63,-1010.63)

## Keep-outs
Keep-Out Layer:
  the board outline again, w4

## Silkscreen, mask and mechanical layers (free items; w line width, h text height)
Top Overlay:
  text "VCC_IO" at -1324.16,-19.99 h40
  text "VS" at -65,-26.66 h32 r90
  text "GND" at -1324,-119.99 h40
  text "GND" at -65,-142.65 h32 r90
  text "CSN" at -1325,-219.99 h40
  text "B2" at -171,-219.99 h40
  text "SCK" at -1325,-319.99 h40
  text "B1" at -157.67,-319.99 h40
  text "SDI" at -1325,-419.99 h40
  text "A2" at -171,-419.99 h40
  text "SDO" at -1325,-519.99 h35
  text "A1" at -157.67,-519.99 h40
  text "V'.BoardVersion'" at -495,-558.31 h35 r90
  text "GND" at -170.63,-619.99 h40
  text "DIAG0" at -1325,-652.99 h40
  text "'.BoardName'" at -556.74,-683.69 h35 r90
  text "DIAG1" at -1325,-719.99 h40
  text "GND" at -170.63,-719.99 h40
  text "DRV_ENN" at -1327,-822 h35
  text "DCIN" at -203.95,-859.99 h40
  text "STEP" at -1325,-919.99 h40
  text "DCEN" at -210.62,-939.99 h40
  text "DIR" at -1325,-1019.99 h40
  text "DCO" at -170.63,-1019.99 h40
Bottom Overlay:
  lines w8: -50,-550 -50,-150
  text "VCC_IO" at -1104.07,-19.99 h40
  text "VS" at -73.37,-20 h40
  text "GND" at -1218.37,-119.99 h40
  text "GND" at -73.37,-120 h40
  text "CSN" at -1218.37,-219.99 h40
  text "B2" at -67,-219.99 h40
  text "SCK" at -1218.37,-319.99 h40
  text "B1" at -69,-319.99 h40
  text "SDI" at -1231.7,-419.99 h40
  text "A2" at -76,-419.99 h40
  text "SDO" at -1218.37,-519.99 h40
  text "A1" at -76,-519.99 h40
  text "DIAG0" at -1145.06,-619.99 h40
  text "GND" at -76,-619.99 h40
  text "DIAG1" at -1158.39,-719.99 h40
  text "GND" at -76,-719.99 h40
  text "V.BoardVersion" at -933.68,-749 h50
  text ".BoardName" at -360.68,-749 h50
  text "Chip: TMC2160-TA" at -353.68,-819 h60
  text "DRV_ENN" at -1058.42,-819.99 h40
  text "DCIN" at -76,-819.99 h40
  text "VSupply: 9…36V" at -353.68,-889 h60
  text "STEP" at -1178.38,-919.99 h40
  text "DCEN" at -76,-919.99 h40
  text "Iphase, RMS: 2.8A" at -353.68,-959 h60
  text "DIR" at -1225.03,-1019.99 h40
  text "DCO" at -76,-1019.99 h40
TopAsm:
  text ".BoardName" at -1327.21,-191.31 h40 r270
  text ".BoardVersion" at -1333.88,-654 h40 r270

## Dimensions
10.63,-1050 to 10.63,50 on Dimension
-1450,10.63 to 50,10.63 on Dimension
